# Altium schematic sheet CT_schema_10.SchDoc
size 277 x 170 mm
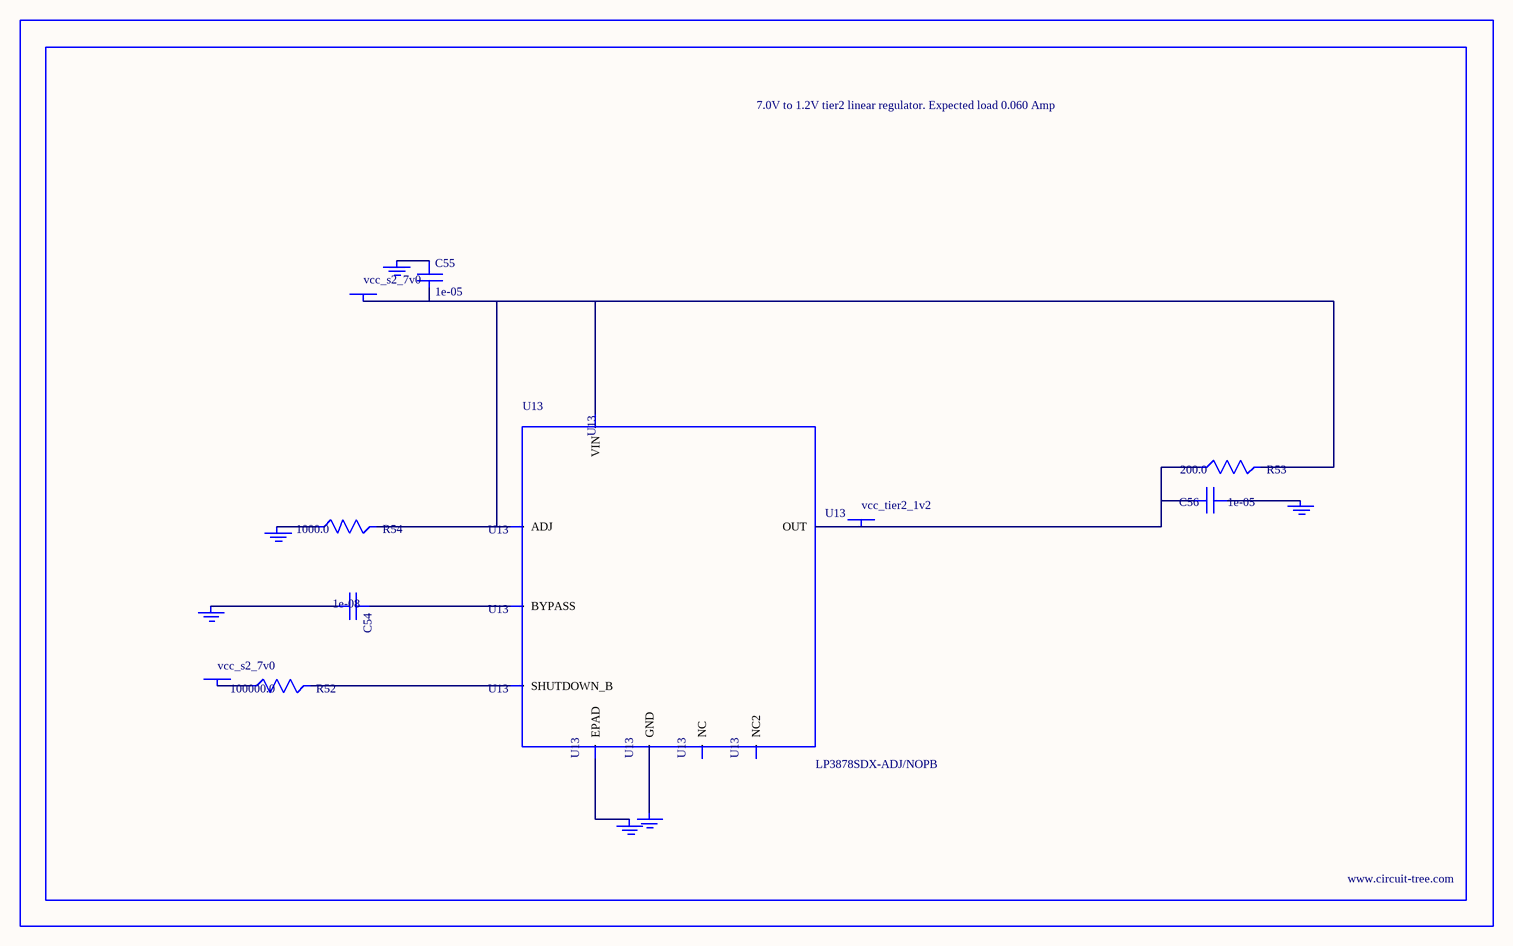
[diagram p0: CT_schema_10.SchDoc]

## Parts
BORDER9  (no value)
C54  1e-08  [C0402]
C55  1e-05  [C1206]
C56  1e-05  [C0805]
GND_INSTANCE_9_0  (no value)
GND_INSTANCE_9_1  (no value)
GND_INSTANCE_9_2  (no value)
GND_INSTANCE_9_3  (no value)
GND_INSTANCE_9_4  (no value)
GND_INSTANCE_9_5  (no value)
POWER_INSTANCE_9_0  vcc_s2_7v0
POWER_INSTANCE_9_1  vcc_s2_7v0
POWER_INSTANCE_9_2  vcc_tier2_1v2
R52  100000.0  [R0603]
R53  200.0  [R0603]
R54  1000.0  [R0603]
U13  LP3878SDX-ADJ/NOPB  [WSON-8]

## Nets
NetC54_1: C54.1 U13.1(BYPASS)
NetC54_2: C54.2 GND_INSTANCE_9_0.0(GND)
NetC55_1: C55.1 GND_INSTANCE_9_1.0(GND)
NetC55_2: C55.2 POWER_INSTANCE_9_0.0(PWR) R53.2 R54.2 U13.4(VIN) U13.6(ADJ)
NetC56_1: C56.1 GND_INSTANCE_9_2.0(GND)
NetC56_2: C56.2 POWER_INSTANCE_9_2.0(PWR) R53.1 U13.5(OUT)
NetGND_INSTANCE_9_3_0: GND_INSTANCE_9_3.0(GND) R54.1
NetGND_INSTANCE_9_4_0: GND_INSTANCE_9_4.0(GND) U13.PAD(EPAD)
NetGND_INSTANCE_9_5_0: GND_INSTANCE_9_5.0(GND) U13.3(GND)
NetPOWER_INSTANCE_9_1_0: POWER_INSTANCE_9_1.0(PWR) R52.1
NetR52_2: R52.2 U13.8(SHUTDOWN_B)

Not connected (* = marked no-connect by the designer): U13 2(NC) 7(NC2)

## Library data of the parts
BORDER9 = BORDER_PAGE9
C54 = C0402C103K3RAC
C55 = C1206C106K3RACTU
C56 = GRM219R60J106ME19D
GND_INSTANCE_9_0-GND_INSTANCE_9_5 = GND
POWER_INSTANCE_9_0-POWER_INSTANCE_9_2 = PWR
R52 = RC0603JR-07100KL
R53 = RC0603JR-07200RL
R54 = RC0603JR-071KL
